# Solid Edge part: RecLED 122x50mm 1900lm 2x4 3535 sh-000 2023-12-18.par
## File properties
Author: robert.pupel
Template: iso metric part.par
Last saved by: robert.pupel
Revision: 7
Application: Solid Edge
Gęstość: 0.000 kg/m^3
Dokładność: 0.990
Username: robert.pupel
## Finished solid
Body 1: solid body, 1133 faces, 2925 edges, 1864 vertices.
  Faces by surface: plane 567, cylinder 290, torus 112, cone 88, spline 46, sphere 28, swept 2
  Edges by curve: line 1538, curve on surface 725, circle 370, spline 160, ellipse 132
Bounding box of the edges (mm; curved faces can reach further): 4.950 x 121.400 x 49.500, from (-1.5, -60.7, -24.75) to (3.45, 60.7, 24.75).
Cylindrical faces by radius (mm): R0.15 x16, R0.199 x2, R0.2 x78, R0.2002 x4, R0.2169 x6, R0.25 x24, R0.3 x4, R0.3373 x6, R0.4 x16, R0.4006 x4, R0.4008 x4, R0.525 x4, R0.6 x24, R0.65 x16, R1 x14, R1.05 x8, R1.0894 x4, R1.0991 x8, R1.1 x28, R1.5309 x1, R1.5312 x1, R1.5314 x1, R1.5316 x1, R1.7414 x1, R1.7423 x1, R1.7453 x1, R1.7463 x1, R1.75 x2, R4.6937 x1, R6.6787 x1, R6.7484 x1, R6.9973 x1, R7.349 x1, R9.2334 x1, R9.8311 x1, R9.8455 x1, R12.245 x1, R15.7879 x1
Conical faces (half-angle, radius in mm at the cone's reference point): 0.3913 deg R1.0968 x4, 0.447 deg R1.0952 x4, 0.464 deg R1.0955 x4, 0.5 deg R0.5056 x8, 0.5 deg R1.0082 x8, 1 deg R0.5511 x4, 10 deg R0.2132 x4, 10 deg R0.4132 x4, 15.6748 deg R1.1041 x2, 15.6751 deg R1.1041 x2, 15.7937 deg R1.1267 x2, 15.7938 deg R1.1267 x2, 18.4844 deg R1.0657 x8, 18.9316 deg R0.5099 x4, 19.4337 deg R0.5111 x4, 27.363 deg R0.6214 x4, 40.1968 deg R0.519 x2, 40.228 deg R0.5176 x2, 42.9179 deg R0.4919 x2, 42.9331 deg R0.4916 x2, 45 deg R0.575 x4, 45 deg R0.625 x8
Toroidal faces (ring radius, tube radius in mm): R0.0958 r0.3997 x8, R0.1 r0.2 x2, R0.1075 r0.4 x4, R0.1101 r0.4001 x4, R0.1216 r0.4 x4, R0.1234 r0.4 x4, R0.1634 r0.2287 x2, R0.1641 r0.2287 x2, R0.3286 r0.2001 x2, R0.3702 r0.4 x4, R0.3818 r0.2 x4, R0.4163 r0.3984 x4, R0.4824 r0.2001 x2, R0.4952 r0.2 x2, R0.6008 r0.3968 x4, R0.6009 r0.3969 x4, R0.6227 r0.2 x2, R0.6235 r0.2 x2, R0.8 r0.2 x8, R0.8522 r0.3 x4, R0.9002 r0.2 x2, R0.9018 r0.2 x2, R0.9181 r0.2227 x4, R0.9197 r0.223 x2, R0.9199 r0.223 x2, R0.9663 r0.2263 x2, R0.9665 r0.2263 x2, R1.3 r0.2 x4, R1.327 r1.1 x4, R1.3271 r1.1 x4, R1.8254 r0.13 x8, R1.8741 r0.2175 x2, R1.8987 r0.2 x2
Spherical faces by radius (mm): R0.2 x16, R0.6 x4, R1.7 x8
Planar faces by outward normal: +x 81, +y 61, +z 57, -x 23, -y 80, -z 57, oblique 208
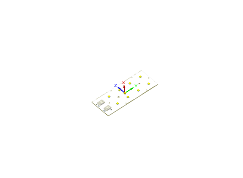
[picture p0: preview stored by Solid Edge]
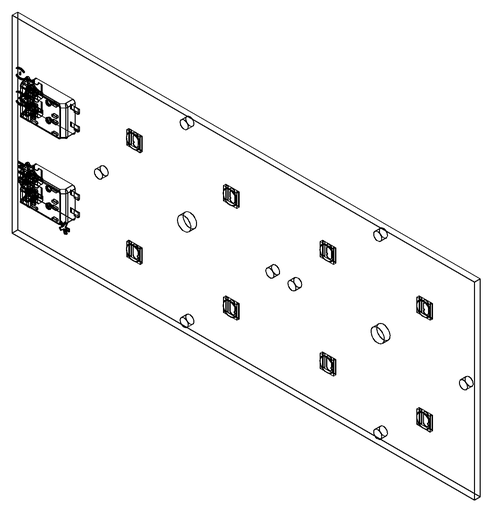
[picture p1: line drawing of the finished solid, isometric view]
